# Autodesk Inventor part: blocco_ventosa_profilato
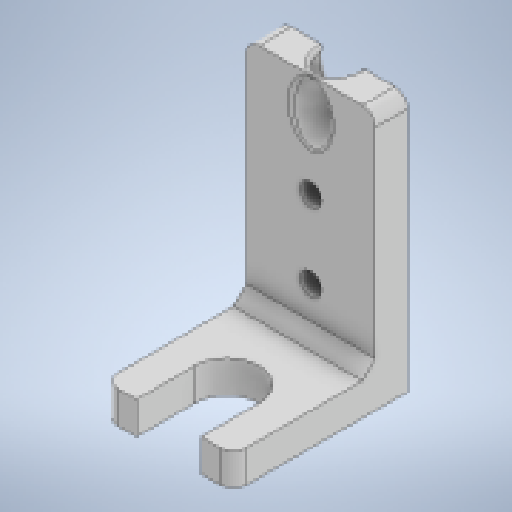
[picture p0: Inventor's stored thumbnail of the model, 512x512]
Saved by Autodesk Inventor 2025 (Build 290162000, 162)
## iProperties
Created: 2026-03
Part Number: blocco_ventosa_profilato
Material: Generico
Document SubType Name: Modeling
Designer: Ryzen5700u
Density: 1 g/cm^3
Appearance: Default
Author: Ryzen5700u
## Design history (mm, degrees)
sketch "Schizzo1"
  geometry: L1 (10, 18)-(-10, 18); L2 (-10, 18)-(-10, -18); L3 (-10, -18)-(10, -18); L4 (10, -18)-(10, 18); L5 (10, 18)-(-10, -18); L6 (-10, 18)-(10, -18); L7 (10, 0)-(-10, 0); L8 (10, 9)-(-10, 9); L9 (5, 0)-(5, 9); L10 (-5, 0)-(-5, 9); A1 r 5 centre (0, 0) between (5, 0) and (-5, 0); 4 further points
  constraints: 20 end point, 6 point on line, 5 midpoint, 4 perpendicular, 2 parallel, 2 point on circle, 1 centre point, 1 coincident, 1 horizontal, 1 tangent
  dimensions: "d0" = 10 diameter of A1; "d1" = 20 distance of L3.end L2.end; "d2" = 36 distance of L2.end L1.end; "d17" = 9 distance from line of point (0, 0) L8
extrude "Estrusione1" new body sketch "Schizzo1" distance "d3" = 5; taper "d4" = 0 deg
sketch "Schizzo2"
  geometry: L1 (-10, 18)-(10, 18); L2 (10, 18)-(10, 13); L3 (10, 13)-(-10, 13); L4 (-10, 13)-(-10, 18); 8 further points
  constraints: 8 end point, 2 parallel, 1 horizontal, 1 perpendicular, 3 other
  dimensions: "d5" = 5 distance of L1.end L2.end
extrude "Estrusione2" join sketch "Schizzo2" distance "d6" = 35; taper "d7" = 0 deg
sketch "Schizzo3"
  geometry: L1 (0, 35)-(20, 35) reference; L2 (3, 0)-(14, 0) reference; L3 (10, 35)-(10, -5); 4 further points
  constraints: 2 end point, 2 point on line, 1 midpoint, 1 perpendicular
  dimensions: "d8" = 16 distance from line of L1 point (10, 19); "d9" = 12 distance of point (10, 19) point (10, 7)
hole "Foro1" sketch "Schizzo3" at (10, 19), (10, 7) diameter "d10" = 3.4; stored, may be unused: countersink angle "d14" = 90 deg, drill point angle "d16" = 118 deg; dims "d11" = 6, "d12" = 6.5, "d13" = 3.4, "d15" = 8
fillet "Raccordo1" dims "d18" = 2
chamfer "Smusso1" distance "d19" = 2; stored, may be unused: second distance "d20" = 2, angle "d21" = 45 deg
sketch "Schizzo4"
  geometry: L1 (0, 0)-(20, 0) reference; L2 (10, 0)-(10, -2); C1 r 0.5 at (10, -2); 3 further points
  constraints: 2 end point, 1 centre point, 1 coincident, 1 midpoint, 1 vertical
  dimensions: "d22" = 2 distance of L2.start L2.end; "d23" = 1 diameter of C1
extrude "Estrusione3" cut sketch "Schizzo4" distance "d24" = 30; taper "d25" = 0 deg
fillet "Raccordo3" dims "d27" = 2
node "Piano di lavoro1"
sketch "Schizzo5"
  geometry: L1 (3, -27.032)-(-13, -27.032) reference; L2 (-5, -27.032)-(-5, -22.532); 2 further points
  constraints: 2 end point, 1 coincident, 1 midpoint, 1 vertical
  dimensions: "d29" = -4.5 distance of L2.start L2.end
hole "Foro2" sketch "Schizzo5" at (-5, -22.532) diameter "d30" = 6.5; stored, may be unused: countersink angle "d34" = 90 deg, drill point angle "d36" = 118 deg; dims "d31" = 6, "d32" = 4, "d33" = 2, "d35" = 8
fillet "Raccordo4" dims "d37" = 0.5
node "Solido1"
other parameters: "d28" = -35 deg
